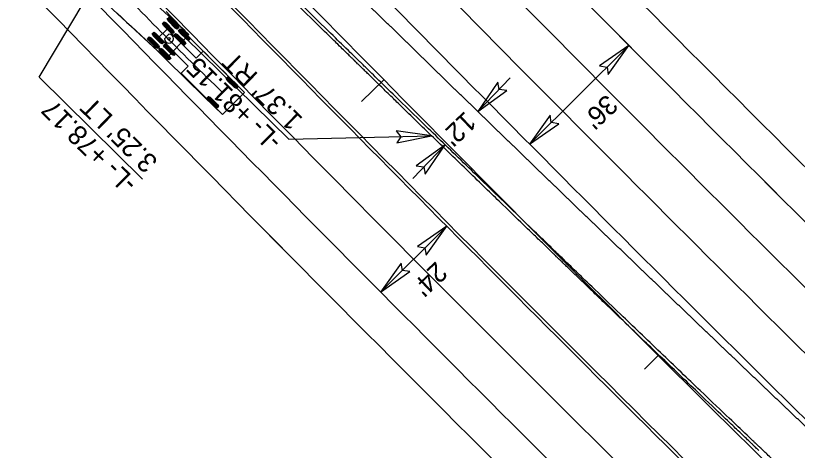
# Model space of a CAD drawing. Extents: x 1262642 to 1268358, y 767825 to 773481.
# Drawn here: x 1266837.7 to 1267038.7, y 771919.2 to 772031 of the extents above; entities that cross this region are included whole.
import ezdxf

# ---------------------------------------------------------------- set-up
doc = ezdxf.new("R2010")
doc.units = 0
for name, color, linetype in [('Prop Conc 1ft 6in Curb and Gutter', 7, 'Continuous'), ('Prop Dimension Text', 7, 'Continuous'), ('Prop EOT', 7, 'Continuous'), ('Prop Horizontal Alignment', 7, 'Continuous'), ('Prop Horizontal Alignment Tick Large', 7, 'Continuous'), ('Prop Horizontal Alignment Tick Small', 7, 'Continuous'), ('Prop Lane Lines', 7, 'Continuous'), ('Prop Paved Shoulder', 7, 'Continuous'), ('Prop Shade Light', 7, 'Continuous'), ('Prop Terminator CELL', 7, 'Continuous'), ('Scratch_Level_3', 7, 'Continuous')]:
    doc.layers.add(name, color=color, linetype=linetype)

msp = doc.modelspace()

# ---------------------------------------------------------------- linework, layer by layer
at = {"layer": 'Prop Conc 1ft 6in Curb and Gutter'}
msp.add_line((1266945.1, 771999.67), (1266944.63, 772000.13), dxfattribs=at)
for points in [[(1266926.16, 772018.12), (1266926.16, 772018.12), (1266926.16, 772018.12), (1266926.16, 772018.12)], [(1266977.31, 771968.49), (1266977.31, 771968.49), (1266977.31, 771968.49), (1266977.31, 771968.49)]]:
    msp.add_lwpolyline(points, dxfattribs=at)
msp.add_arc((1275047.31, 780021.23), 11414.25, 223.957867, 225.419319, dxfattribs=at)
for points in [[(1266926.16, 772018.12), (1266925.89, 772018.38), (1266925.63, 772018.64), (1266925.23, 772019.03), (1266925.1, 772019.16), (1266924.9, 772019.35), (1266924.83, 772019.42), (1266924.7, 772019.55), (1266924.63, 772019.61), (1266924.03, 772020.2), (1266923.5, 772020.72), (1266921.91, 772022.27), (1266920.85, 772023.31), (1266917.66, 772026.43), (1266911.29, 772032.66), (1266900.69, 772043.06), (1266892.23, 772051.39), (1266885.88, 772057.64), (1266883.77, 772059.73), (1266880.6, 772062.86), (1266879.54, 772063.9), (1266878.35, 772065.08), (1266878.22, 772065.21), (1266878.02, 772065.4), (1266877.95, 772065.47), (1266877.82, 772065.6), (1266877.76, 772065.66), (1266877.43, 772065.99), (1266877.16, 772066.25), (1266876.63, 772066.77), (1266876.37, 772067.03), (1266875.84, 772067.55), (1266875.58, 772067.81), (1266875.31, 772068.07)], [(1266944.63, 772000.13), (1266942.72, 772001.98), (1266940.82, 772003.83), (1266936.79, 772007.76), (1266934.66, 772009.83), (1266931.47, 772012.94), (1266930.41, 772013.97), (1266928.82, 772015.53), (1266928.28, 772016.05), (1266927.22, 772017.08), (1266926.69, 772017.6), (1266926.16, 772018.12)], [(1266977.31, 771968.49), (1266977.04, 771968.75), (1266976.78, 771969.01), (1266976.37, 771969.39), (1266976.24, 771969.52), (1266976.04, 771969.72), (1266975.97, 771969.78), (1266975.84, 771969.91), (1266975.77, 771969.97), (1266975.17, 771970.55), (1266974.64, 771971.07), (1266973.04, 771972.62), (1266971.97, 771973.65), (1266968.76, 771976.74), (1266962.36, 771982.93), (1266953.76, 771991.26), (1266947.3, 771997.54), (1266945.1, 771999.67)], [(1267028.76, 771919.19), (1267028.5, 771919.45), (1267028.23, 771919.7), (1267027.82, 771920.09), (1267027.69, 771920.21), (1267027.49, 771920.41), (1267027.42, 771920.47), (1267027.29, 771920.6), (1267027.22, 771920.66), (1267026.61, 771921.24), (1267026.08, 771921.75), (1267024.46, 771923.29), (1267023.39, 771924.31), (1267020.17, 771927.38), (1267013.72, 771933.53), (1267003, 771943.8), (1266994.43, 771952.02), (1266988, 771958.19), (1266985.86, 771960.25), (1266982.66, 771963.34), (1266981.59, 771964.37), (1266979.98, 771965.92), (1266979.45, 771966.43), (1266978.38, 771967.46), (1266977.85, 771967.98), (1266977.31, 771968.49)]]:
    msp.add_open_spline(points, degree=3, dxfattribs=at)
at = {"layer": 'Prop Dimension Text'}
for p, q in [((1266881.31, 772025.39), (1266907.89, 771999.2)), ((1266995.37, 772023.34), (1266969.83, 771997.97)), ((1266870.33, 771988.98), (1266843.75, 772015.18)), ((1266956.51, 772006.37), (1266964.87, 772014.97)), ((1266939.79, 771989.15), (1266948.15, 771997.76)), ((1266948.54, 771976.83), (1266931.52, 771959.92))]:
    msp.add_line(p, q, dxfattribs=at)
for points in [[(1266843.75, 772015.18), (1266875.31, 772068.07)], [(1266907.89, 771999.2), (1266944.63, 772000.13)]]:
    msp.add_lwpolyline(points, dxfattribs=at)
at = {"layer": 'Prop EOT'}
for points in [[(1266926.68, 772018.66), (1266926.68, 772018.66), (1266926.68, 772018.66)], [(1266977.83, 771969.03), (1266977.83, 771969.03), (1266977.83, 771969.03)], [(1267029.28, 771919.73), (1267029.28, 771919.73), (1267029.28, 771919.73)]]:
    msp.add_lwpolyline(points, dxfattribs=at)
for radius, start, end in [(11349, 223.976844, 225.401912), (11415, 224.252026, 225.404319), (11439, 224.175182, 225.443384)]:
    msp.add_arc((1275047.31, 780021.23), radius, start, end, dxfattribs=at)
for points in [[(1266926.68, 772018.66), (1266926.42, 772018.92), (1266926.02, 772019.31), (1266925.62, 772019.7), (1266925.42, 772019.89), (1266925.36, 772019.96), (1266925.22, 772020.09), (1266924.62, 772020.67), (1266922.97, 772022.29), (1266919.25, 772025.92), (1266911.82, 772033.19), (1266901.22, 772043.59), (1266890.64, 772054.01), (1266883.24, 772061.3), (1266879.93, 772064.57), (1266878.75, 772065.74), (1266878.55, 772065.93), (1266878.48, 772066), (1266878.35, 772066.13), (1266878.02, 772066.46), (1266877.69, 772066.78), (1266877.16, 772067.3), (1266876.9, 772067.57), (1266876.37, 772068.09), (1266876.11, 772068.35), (1266875.84, 772068.61)], [(1266977.83, 771969.03), (1266977.56, 771969.29), (1266977.16, 771969.68), (1266976.76, 771970.06), (1266976.56, 771970.26), (1266976.49, 771970.32), (1266976.36, 771970.45), (1266975.76, 771971.03), (1266974.09, 771972.64), (1266970.35, 771976.25), (1266962.88, 771983.47), (1266952.21, 771993.8), (1266941.57, 772004.15), (1266934.12, 772011.4), (1266930.4, 772015.03), (1266928.81, 772016.58), (1266927.75, 772017.62), (1266927.21, 772018.14), (1266926.68, 772018.66)], [(1267029.28, 771919.73), (1267029.01, 771919.99), (1267028.61, 771920.37), (1267028.21, 771920.76), (1267028, 771920.95), (1267027.94, 771921.01), (1267027.8, 771921.14), (1267027.2, 771921.72), (1267025.52, 771923.32), (1267021.76, 771926.9), (1267014.24, 771934.08), (1267003.51, 771944.34), (1266992.8, 771954.62), (1266985.31, 771961.82), (1266981.57, 771965.43), (1266979.97, 771966.97), (1266978.9, 771968), (1266978.37, 771968.52), (1266977.83, 771969.03)], [(1267080.98, 771870.69), (1267072.36, 771878.86), (1267061.59, 771889.07), (1267049.74, 771900.3), (1267046.48, 771903.39), (1267045.37, 771904.44), (1267045.33, 771904.48), (1267045.32, 771904.49), (1267045.3, 771904.51), (1267045.28, 771904.53), (1267045.18, 771904.62), (1267045.1, 771904.7), (1267044.9, 771904.89), (1267044.76, 771905.02), (1267044.36, 771905.41), (1267043.95, 771905.79), (1267043.55, 771906.17), (1267043.35, 771906.36), (1267043.28, 771906.43), (1267043.14, 771906.56), (1267042.81, 771906.87), (1267040.32, 771909.24), (1267036.82, 771912.57), (1267033.05, 771916.15), (1267031.43, 771917.68), (1267030.36, 771918.71), (1267029.82, 771919.22), (1267029.28, 771919.73)]]:
    msp.add_open_spline(points, degree=3, dxfattribs=at)
at = {"layer": 'Prop Horizontal Alignment'}
msp.add_arc((1275047.31, 780021.23), 11400, 222.993587, 225.404319, dxfattribs=at)
at = {"layer": 'Prop Horizontal Alignment Tick Large'}
msp.add_line((1266932.35, 772014.51), (1266926.66, 772008.89), dxfattribs=at)
at = {"layer": 'Prop Horizontal Alignment Tick Small'}
msp.add_line((1267002.9, 771943.63), (1266999.37, 771940.09), dxfattribs=at)
at = {"layer": 'Prop Lane Lines'}
for radius, start, end in [(11427, 222.993587, 225.36373), (11361, 224.221214, 225.404319), (11373, 224.221214, 225.404319), (11385, 224.221214, 225.404319)]:
    msp.add_arc((1275047.31, 780021.23), radius, start, end, dxfattribs=at)
for points in [[(1266935.07, 772027.24), (1266934.38, 772027.92), (1266933.69, 772028.59), (1266933, 772029.26), (1266932.31, 772029.93), (1266931.62, 772030.61), (1266930.94, 772031.28), (1266930.25, 772031.95), (1266929.56, 772032.62), (1266928.87, 772033.3), (1266928.18, 772033.97), (1266927.5, 772034.64), (1266926.81, 772035.31), (1266926.12, 772035.99), (1266925.43, 772036.66), (1266924.75, 772037.33), (1266924.06, 772038.01), (1266923.37, 772038.68), (1266922.68, 772039.35), (1266922, 772040.03), (1266921.31, 772040.7), (1266920.62, 772041.37), (1266919.93, 772042.05), (1266919.25, 772042.72), (1266918.56, 772043.39), (1266917.87, 772044.07), (1266917.19, 772044.74), (1266916.5, 772045.41), (1266915.81, 772046.09), (1266915.13, 772046.76), (1266914.44, 772047.43), (1266913.75, 772048.11), (1266913.07, 772048.78), (1266912.38, 772049.46), (1266911.69, 772050.13), (1266911.01, 772050.81), (1266910.32, 772051.48), (1266909.63, 772052.15), (1266908.95, 772052.83), (1266908.26, 772053.5), (1266907.57, 772054.18), (1266906.89, 772054.85), (1266906.2, 772055.53), (1266905.52, 772056.2), (1266904.83, 772056.88), (1266904.14, 772057.55), (1266903.46, 772058.22), (1266902.77, 772058.9), (1266902.09, 772059.57), (1266901.4, 772060.25), (1266900.72, 772060.92), (1266900.03, 772061.6), (1266899.34, 772062.27), (1266898.66, 772062.95), (1266897.97, 772063.63), (1266897.29, 772064.3), (1266896.6, 772064.98), (1266895.92, 772065.65), (1266895.23, 772066.33), (1266894.55, 772067), (1266893.86, 772067.68), (1266893.18, 772068.35), (1266892.49, 772069.03), (1266891.81, 772069.71), (1266891.12, 772070.38), (1266890.44, 772071.06), (1266889.75, 772071.73), (1266889.07, 772072.41), (1266888.38, 772073.09), (1266887.7, 772073.76), (1266887.01, 772074.44), (1266886.33, 772075.11), (1266885.65, 772075.79), (1266884.28, 772077.14)], [(1266986.16, 771977.67), (1266985.47, 771978.34), (1266984.78, 771979.01), (1266984.08, 771979.67), (1266983.39, 771980.34), (1266982.7, 771981.01), (1266982.01, 771981.68), (1266981.31, 771982.35), (1266980.62, 771983.01), (1266979.93, 771983.68), (1266979.24, 771984.35), (1266978.55, 771985.02), (1266977.85, 771985.69), (1266977.16, 771986.36), (1266976.47, 771987.02), (1266975.78, 771987.69), (1266975.09, 771988.36), (1266974.4, 771989.03), (1266973.7, 771989.7), (1266973.01, 771990.37), (1266972.32, 771991.04), (1266971.63, 771991.71), (1266970.94, 771992.38), (1266970.25, 771993.04), (1266969.56, 771993.71), (1266968.86, 771994.38), (1266968.17, 771995.05), (1266967.48, 771995.72), (1266966.79, 771996.39), (1266966.1, 771997.06), (1266965.41, 771997.73), (1266964.72, 771998.4), (1266964.03, 771999.07), (1266963.34, 771999.74), (1266962.65, 772000.41), (1266961.96, 772001.08), (1266961.27, 772001.75), (1266960.58, 772002.42), (1266959.88, 772003.09), (1266959.19, 772003.76), (1266958.5, 772004.43), (1266957.81, 772005.1), (1266957.12, 772005.77), (1266956.43, 772006.44), (1266955.74, 772007.11), (1266955.05, 772007.78), (1266954.36, 772008.45), (1266953.67, 772009.12), (1266952.98, 772009.79), (1266952.29, 772010.46), (1266951.6, 772011.13), (1266950.91, 772011.8), (1266950.22, 772012.47), (1266949.53, 772013.14), (1266948.85, 772013.81), (1266948.16, 772014.49), (1266947.47, 772015.16), (1266946.78, 772015.83), (1266946.09, 772016.5), (1266945.4, 772017.17), (1266944.71, 772017.84), (1266944.02, 772018.51), (1266943.33, 772019.18), (1266942.64, 772019.86), (1266941.95, 772020.53), (1266941.26, 772021.2), (1266940.58, 772021.87), (1266939.89, 772022.54), (1266939.2, 772023.21), (1266938.51, 772023.89), (1266937.82, 772024.56), (1266937.13, 772025.23), (1266936.44, 772025.9), (1266935.75, 772026.57), (1266935.07, 772027.24)], [(1267037.56, 771928.42), (1267036.86, 771929.09), (1267036.16, 771929.75), (1267035.47, 771930.41), (1267034.77, 771931.08), (1267034.07, 771931.74), (1267033.38, 771932.4), (1267032.68, 771933.07), (1267031.99, 771933.73), (1267031.29, 771934.4), (1267030.59, 771935.06), (1267029.9, 771935.72), (1267029.2, 771936.39), (1267028.51, 771937.05), (1267027.81, 771937.72), (1267027.11, 771938.38), (1267026.42, 771939.04), (1267025.72, 771939.71), (1267025.03, 771940.37), (1267024.33, 771941.04), (1267023.64, 771941.7), (1267022.94, 771942.37), (1267022.25, 771943.03), (1267021.55, 771943.7), (1267020.85, 771944.36), (1267020.16, 771945.02), (1267019.46, 771945.69), (1267018.77, 771946.35), (1267018.07, 771947.02), (1267017.38, 771947.68), (1267016.68, 771948.35), (1267015.99, 771949.01), (1267015.29, 771949.68), (1267014.6, 771950.34), (1267013.9, 771951.01), (1267013.21, 771951.68), (1267012.52, 771952.34), (1267011.82, 771953.01), (1267011.13, 771953.67), (1267010.43, 771954.34), (1267009.74, 771955), (1267009.04, 771955.67), (1267008.35, 771956.33), (1267007.65, 771957), (1267006.96, 771957.67), (1267006.27, 771958.33), (1267005.57, 771959), (1267004.88, 771959.66), (1267004.18, 771960.33), (1267003.49, 771961), (1267002.8, 771961.66), (1267002.1, 771962.33), (1267001.41, 771963), (1267000.71, 771963.66), (1267000.02, 771964.33), (1266999.33, 771965), (1266998.63, 771965.66), (1266997.94, 771966.33), (1266997.25, 771967), (1266996.55, 771967.66), (1266995.86, 771968.33), (1266995.17, 771969), (1266994.47, 771969.66), (1266993.78, 771970.33), (1266993.09, 771971), (1266992.39, 771971.66), (1266991.7, 771972.33), (1266991.01, 771973), (1266990.32, 771973.67), (1266989.62, 771974.33), (1266988.93, 771975), (1266988.24, 771975.67), (1266987.55, 771976.34), (1266986.85, 771977), (1266986.16, 771977.67)], [(1267089.23, 771879.4), (1267088.53, 771880.06), (1267087.84, 771880.72), (1267087.14, 771881.38), (1267086.44, 771882.05), (1267085.74, 771882.71), (1267085.04, 771883.37), (1267084.34, 771884.04), (1267083.64, 771884.7), (1267082.94, 771885.36), (1267082.24, 771886.02), (1267081.55, 771886.69), (1267080.85, 771887.35), (1267080.15, 771888.01), (1267079.45, 771888.67), (1267078.75, 771889.34), (1267078.05, 771890), (1267077.35, 771890.66), (1267076.65, 771891.32), (1267075.95, 771891.99), (1267075.26, 771892.65), (1267074.56, 771893.31), (1267073.86, 771893.97), (1267073.16, 771894.64), (1267072.46, 771895.3), (1267071.76, 771895.96), (1267071.06, 771896.62), (1267070.36, 771897.29), (1267069.66, 771897.95), (1267068.97, 771898.61), (1267068.27, 771899.27), (1267067.57, 771899.94), (1267066.87, 771900.6), (1267066.17, 771901.26), (1267065.47, 771901.92), (1267064.77, 771902.59), (1267064.07, 771903.25), (1267063.37, 771903.91), (1267062.68, 771904.57), (1267061.98, 771905.24), (1267061.28, 771905.9), (1267060.58, 771906.56), (1267059.88, 771907.22), (1267059.18, 771907.89), (1267058.48, 771908.55), (1267057.78, 771909.21), (1267057.08, 771909.87), (1267056.39, 771910.54), (1267055.69, 771911.2), (1267054.99, 771911.86), (1267054.29, 771912.52), (1267053.59, 771913.19), (1267052.89, 771913.85), (1267052.2, 771914.51), (1267051.5, 771915.17), (1267050.8, 771915.83), (1267050.1, 771916.49), (1267049.41, 771917.16), (1267048.71, 771917.82), (1267048.01, 771918.48), (1267047.31, 771919.14), (1267046.62, 771919.81), (1267045.92, 771920.47), (1267045.22, 771921.13), (1267044.53, 771921.79), (1267043.83, 771922.46), (1267043.13, 771923.12), (1267042.43, 771923.78), (1267041.74, 771924.44), (1267041.04, 771925.11), (1267040.34, 771925.77), (1267039.65, 771926.43), (1267038.95, 771927.1), (1267038.25, 771927.76), (1267037.56, 771928.42)]]:
    msp.add_spline(points, degree=3, dxfattribs=at)
at = {"layer": 'Prop Paved Shoulder'}
for radius, start, end in [(11339, 223.976889, 225.401912), (11449, 223.936318, 225.443384)]:
    msp.add_arc((1275047.31, 780021.23), radius, start, end, dxfattribs=at)
at = {"layer": 'Prop Shade Light'}
for centre, radius, start, end in [((1275047.31, 780021.22), 11339, 223.976889, 225.401893), ((1275047.31, 780021.22), 11349, 223.976844, 225.401912), ((1275047.31, 780021.23), 11449, 223.936318, 225.443367), ((1275047.31, 780021.23), 11439, 224.175182, 225.443384)]:
    msp.add_arc(centre, radius, start, end, dxfattribs=at)
at = {"layer": 'Prop Terminator CELL'}
for points in [[(1266990.08, 772015.9), (1266995.37, 772023.34), (1266987.82, 772018.1), (1266989.77, 772017.78)], [(1266961.67, 772013.9), (1266956.51, 772006.37), (1266963.96, 772011.74), (1266962.01, 772012.03)], [(1266975.12, 772005.41), (1266969.83, 771997.97), (1266977.38, 772003.22), (1266975.43, 772003.54)], [(1266935.69, 771998.27), (1266944.63, 772000.13), (1266935.53, 772001.42), (1266936.73, 771999.86)], [(1266942.99, 771990.22), (1266948.15, 771997.76), (1266940.69, 771992.38), (1266942.64, 771992.09)], [(1266943.25, 771969.39), (1266948.54, 771976.83), (1266941, 771971.59), (1266942.94, 771971.26)], [(1266936.81, 771967.36), (1266931.52, 771959.92), (1266939.07, 771965.16), (1266937.12, 771965.48)]]:
    msp.add_lwpolyline(points, close=True, dxfattribs=at)
at = {"layer": 'Scratch_Level_3'}
for p, q in [((1266882.19, 772026.16), (1266846.96, 772058.76)), ((1266841.19, 772052.52), (1266876.41, 772019.92)), ((1266879.59, 772027.91), (1266877, 772030.51)), ((1266878.1, 772026.43), (1266875.51, 772029.02)), ((1266878.26, 772026.59), (1266875.67, 772029.18)), ((1266878.42, 772026.75), (1266875.84, 772029.35)), ((1266879.27, 772027.59), (1266876.68, 772030.19)), ((1266879.43, 772027.75), (1266876.84, 772030.35)), ((1266875.58, 772023.92), (1266872.99, 772026.51)), ((1266875.74, 772024.08), (1266873.16, 772026.68)), ((1266876.64, 772027.56), (1266874.61, 772025.54)), ((1266884.11, 772020.07), (1266876.64, 772027.56)), ((1266882.21, 772024.64), (1266879.62, 772027.24)), ((1266882.37, 772024.8), (1266879.78, 772027.4)), ((1266882.53, 772024.96), (1266879.95, 772027.56)), ((1266874.25, 772022.59), (1266871.66, 772025.19)), ((1266874.41, 772022.75), (1266871.83, 772025.35)), ((1266874.58, 772022.91), (1266871.99, 772025.51)), ((1266875.42, 772023.76), (1266872.83, 772026.35)), ((1266874.61, 772025.54), (1266882.08, 772018.04)), ((1266877.1, 772026.22), (1266875.96, 772025.08)), ((1266876.41, 772019.92), (1266882.19, 772026.16)), ((1266881.04, 772023.47), (1266878.45, 772026.07)), ((1266881.2, 772023.64), (1266878.62, 772026.23)), ((1266881.37, 772023.8), (1266878.78, 772026.4)), ((1266882.19, 772026.16), (1266882.19, 772026.16)), ((1266877.52, 772019.96), (1266874.93, 772022.56)), ((1266878.36, 772020.8), (1266875.77, 772023.4)), ((1266878.52, 772020.97), (1266875.94, 772023.56)), ((1266878.69, 772021.13), (1266876.1, 772023.72)), ((1266877.19, 772019.64), (1266874.6, 772022.24)), ((1266877.36, 772019.8), (1266874.77, 772022.4)), ((1266885.93, 772021.88), (1266884.11, 772020.07)), ((1266896.52, 772011.25), (1266885.93, 772021.88)), ((1266882.08, 772018.04), (1266880.27, 772016.23)), ((1266880.27, 772016.23), (1266890.85, 772005.61)), ((1266894.53, 772012.33), (1266891.89, 772014.88)), ((1266894.69, 772012.5), (1266892.05, 772015.04)), ((1266894.84, 772012.66), (1266892.21, 772015.21)), ((1266890.85, 772005.61), (1266896.52, 772011.25)), ((1266896.52, 772011.25), (1266896.52, 772011.25)), ((1266889.52, 772007.32), (1266886.88, 772009.86)), ((1266889.68, 772007.48), (1266887.04, 772010.03)), ((1266889.84, 772007.65), (1266887.2, 772010.19))]:
    msp.add_line(p, q, dxfattribs=at)
for points in [[(1266863.75, 772031.64), (1266864.98, 772030.5), (1266866.21, 772029.36), (1266867.44, 772028.22), (1266868.67, 772027.08), (1266869.9, 772025.95), (1266871.13, 772024.81), (1266872.36, 772023.67), (1266873.59, 772022.53), (1266874.78, 772021.34), (1266875.97, 772020.15), (1266877.16, 772018.97), (1266878.35, 772017.79), (1266879.54, 772016.61), (1266880.74, 772015.43), (1266881.93, 772014.25), (1266883.13, 772013.08), (1266884.33, 772011.9), (1266885.54, 772010.73), (1266886.74, 772009.56), (1266887.95, 772008.4), (1266889.16, 772007.23), (1266890.37, 772006.07), (1266890.85, 772005.61)], [(1266876.35, 772032.08), (1266877.51, 772030.89), (1266878.68, 772029.7), (1266879.85, 772028.51), (1266881.02, 772027.32), (1266881.92, 772025.85), (1266883.1, 772024.68), (1266884.29, 772023.51), (1266885.47, 772022.33), (1266886.65, 772021.16), (1266887.82, 772019.98), (1266889, 772018.8), (1266890.17, 772017.62), (1266891.35, 772016.44), (1266892.53, 772015.26), (1266893.7, 772014.08), (1266894.88, 772012.9), (1266896.05, 772011.73), (1266896.52, 772011.25)]]:
    msp.add_lwpolyline(points, dxfattribs=at)
for points in [[(1266879.63, 772027.95), (1266879.23, 772027.55), (1266878.74, 772027.79), (1266876.88, 772029.66), (1266876.64, 772030.15), (1266877.05, 772030.55), (1266877.53, 772030.31), (1266879.39, 772028.44)], [(1266878.46, 772026.79), (1266878.06, 772026.39), (1266877.58, 772026.63), (1266875.71, 772028.5), (1266875.47, 772028.98), (1266875.88, 772029.39), (1266876.36, 772029.14), (1266878.22, 772027.27)], [(1266875.79, 772024.12), (1266875.38, 772023.72), (1266874.9, 772023.96), (1266873.03, 772025.83), (1266872.79, 772026.31), (1266873.2, 772026.72), (1266873.68, 772026.47), (1266875.54, 772024.6)], [(1266882.57, 772025), (1266882.17, 772024.6), (1266881.69, 772024.84), (1266879.82, 772026.71), (1266879.58, 772027.2), (1266879.99, 772027.6), (1266880.47, 772027.36), (1266882.33, 772025.49)], [(1266874.62, 772022.95), (1266874.21, 772022.55), (1266873.73, 772022.79), (1266871.86, 772024.66), (1266871.62, 772025.15), (1266872.03, 772025.55), (1266872.51, 772025.31), (1266874.38, 772023.44)], [(1266881.41, 772023.84), (1266881, 772023.43), (1266880.52, 772023.68), (1266878.65, 772025.55), (1266878.41, 772026.03), (1266878.82, 772026.44), (1266879.3, 772026.19), (1266881.17, 772024.32)], [(1266877.56, 772020), (1266877.15, 772019.6), (1266876.67, 772019.84), (1266874.8, 772021.71), (1266874.56, 772022.2), (1266874.97, 772022.6), (1266875.45, 772022.36), (1266877.32, 772020.49)], [(1266878.73, 772021.17), (1266878.32, 772020.76), (1266877.84, 772021.01), (1266875.97, 772022.88), (1266875.73, 772023.36), (1266876.14, 772023.76), (1266876.62, 772023.52), (1266878.49, 772021.65)], [(1266894.88, 772012.7), (1266894.49, 772012.29), (1266894, 772012.52), (1266892.1, 772014.36), (1266891.85, 772014.84), (1266892.25, 772015.25), (1266892.73, 772015.02), (1266894.63, 772013.18)], [(1266889.88, 772007.69), (1266889.48, 772007.28), (1266888.99, 772007.51), (1266887.09, 772009.34), (1266886.84, 772009.82), (1266887.24, 772010.24), (1266887.73, 772010), (1266889.63, 772008.17)]]:
    msp.add_lwpolyline(points, close=True, dxfattribs=at)
msp.add_circle((1266877.1, 772025.08), 0.34, dxfattribs=at)
for centre, radius, start, end in [((1267582.95, 772728.75), 996.88, 223.4763, 226.03231), ((1266877.1, 772025.08), 1.14, 179.9029, 89.9029)]:
    msp.add_arc(centre, radius, start, end, dxfattribs=at)

# ---------------------------------------------------------------- texts
at = {"layer": 'Prop Dimension Text'}
for s, rotation, p in [("1.37' RT", 135.4239, (1266911.78, 772004.52)), ('-L- +81.15', 135.4239, (1266906.52, 771999.18)), ('-L- +78.17', 135.4239, (1266869.26, 771988.32)), ("3.25' LT", 135.4239, (1266874.52, 771993.66)), ("36'", 223.4955, (1266989.6, 772011.03)), ("12'", 223.4955, (1266953.22, 772006.64)), ("24'", 223.4955, (1266945.76, 771967.98))]:
    msp.add_text(s, height=5, rotation=rotation, dxfattribs=at).set_placement(p)

doc.saveas('drawing.dxf')
